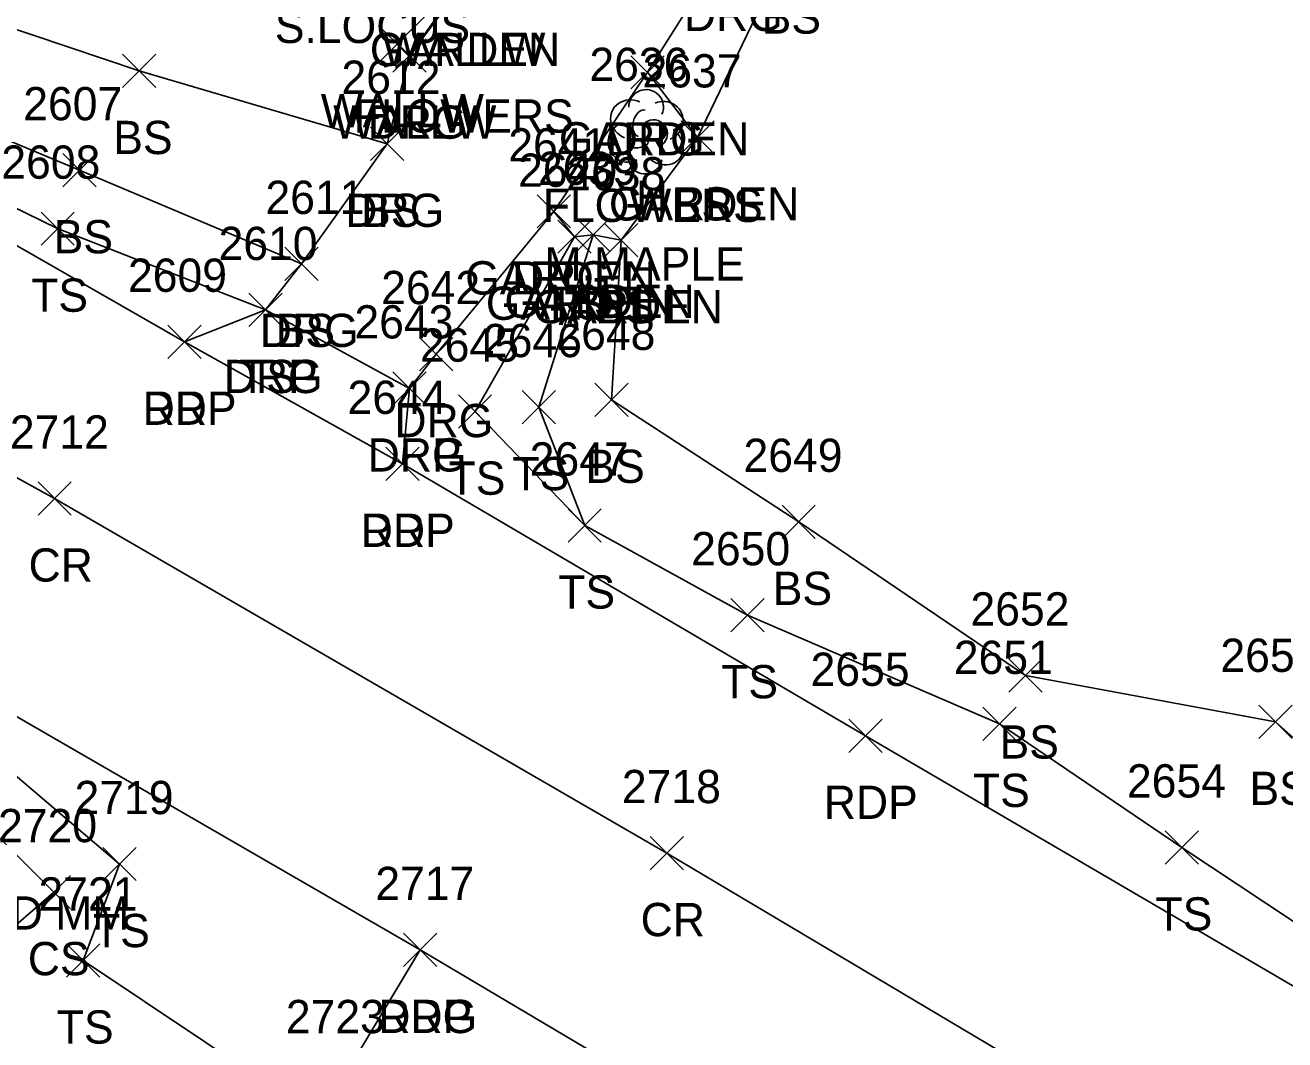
# Model space of a CAD drawing. Extents: x 1499292 to 1501024, y 534584 to 538043.
# Drawn here: x 1499592.5 to 1499668.2, y 537816.8 to 537877.8 of the extents above; entities that cross this region are included whole.
import ezdxf

# ---------------------------------------------------------------- set-up
doc = ezdxf.new("R2010")
doc.units = 0
for name, color, linetype in [('L_A', 7, 'Continuous'), ('L_C', 7, 'Continuous'), ('L_I', 7, 'Continuous'), ('L_TIC', 7, 'Continuous'), ('LAPB', 7, 'Continuous'), ('LELB', 7, 'Continuous'), ('LTD', 7, 'Continuous'), ('LW', 7, 'Continuous'), ('P_A', 7, 'Continuous'), ('P_I', 7, 'Continuous'), ('P_TIC', 7, 'Continuous'), ('PET', 7, 'Continuous'), ('PRC', 7, 'Continuous'), ('R_A', 7, 'Continuous'), ('R_C', 7, 'Continuous'), ('R_I', 7, 'Continuous'), ('R_TIC', 7, 'Continuous'), ('RDG', 7, 'Continuous'), ('RDP', 7, 'Continuous'), ('S_C', 7, 'Continuous')]:
    doc.layers.add(name, color=color, linetype=linetype)

msp = doc.modelspace()

# ---------------------------------------------------------------- linework, layer by layer
at = {"layer": 'L_TIC'}
for points in [[(1499613.859, 537875.659), (1499615.859, 537877.659)], [(1499615.859, 537875.659), (1499613.859, 537877.659)], [(1499614.61, 537874.966), (1499616.61, 537876.966)], [(1499616.61, 537874.966), (1499614.61, 537876.966)], [(1499598.362, 537874.044), (1499600.362, 537876.044)], [(1499600.362, 537874.044), (1499598.362, 537876.044)], [(1499628.919, 537873.961), (1499630.919, 537875.961)], [(1499630.919, 537873.961), (1499628.919, 537875.961)], [(1499613.263, 537869.665), (1499615.263, 537871.665)], [(1499615.263, 537869.665), (1499613.263, 537871.665)], [(1499631.925, 537870.051), (1499633.925, 537872.051)], [(1499633.925, 537870.051), (1499631.925, 537872.051)], [(1499631.925, 537870.051), (1499633.925, 537872.051)], [(1499633.925, 537870.051), (1499631.925, 537872.051)], [(1499594.778, 537868.076), (1499596.778, 537870.076)], [(1499596.778, 537868.076), (1499594.778, 537870.076)], [(1499623.289, 537865.6), (1499625.289, 537867.6)], [(1499625.289, 537865.6), (1499623.289, 537867.6)], [(1499593.46, 537864.561), (1499595.46, 537866.561)], [(1499595.46, 537864.561), (1499593.46, 537866.561)], [(1499624.53, 537864.077), (1499626.53, 537866.077)], [(1499626.53, 537864.077), (1499624.53, 537866.077)], [(1499624.53, 537864.077), (1499626.53, 537866.077)], [(1499626.53, 537864.077), (1499624.53, 537866.077)], [(1499625.646, 537864.191), (1499627.646, 537866.191)], [(1499627.646, 537864.191), (1499625.646, 537866.191)], [(1499625.646, 537864.191), (1499627.646, 537866.191)], [(1499627.646, 537864.191), (1499625.646, 537866.191)], [(1499627.34, 537863.862), (1499629.34, 537865.862)], [(1499629.34, 537863.862), (1499627.34, 537865.862)], [(1499627.34, 537863.862), (1499629.34, 537865.862)], [(1499629.34, 537863.862), (1499627.34, 537865.862)], [(1499608.124, 537862.443), (1499610.124, 537864.443)], [(1499610.124, 537862.443), (1499608.124, 537864.443)], [(1499605.958, 537859.671), (1499607.958, 537861.671)], [(1499607.958, 537859.671), (1499605.958, 537861.671)], [(1499626.747, 537854.268), (1499628.747, 537856.268)], [(1499628.747, 537854.268), (1499626.747, 537856.268)], [(1499626.747, 537854.268), (1499628.747, 537856.268)], [(1499628.747, 537854.268), (1499626.747, 537856.268)], [(1499618.548, 537853.557), (1499620.548, 537855.557)], [(1499620.548, 537853.557), (1499618.548, 537855.557)], [(1499622.386, 537853.831), (1499624.386, 537855.831)], [(1499624.386, 537853.831), (1499622.386, 537855.831)], [(1499625.141, 537846.711), (1499627.141, 537848.711)], [(1499627.141, 537846.711), (1499625.141, 537848.711)], [(1499625.141, 537846.711), (1499627.141, 537848.711)], [(1499627.141, 537846.711), (1499625.141, 537848.711)], [(1499638.004, 537846.929), (1499640.004, 537848.929)], [(1499640.004, 537846.929), (1499638.004, 537848.929)], [(1499634.935, 537841.316), (1499636.935, 537843.316)], [(1499636.935, 537841.316), (1499634.935, 537843.316)], [(1499651.639, 537837.691), (1499653.639, 537839.691)], [(1499653.639, 537837.691), (1499651.639, 537839.691)], [(1499650.071, 537834.781), (1499652.071, 537836.781)], [(1499652.071, 537834.781), (1499650.071, 537836.781)], [(1499666.661, 537834.904), (1499668.661, 537836.904)], [(1499668.661, 537834.904), (1499666.661, 537836.904)], [(1499661.043, 537827.35), (1499663.043, 537829.35)], [(1499663.043, 537827.35), (1499661.043, 537829.35)], [(1499597.177, 537826.35), (1499599.177, 537828.35)], [(1499599.177, 537826.35), (1499597.177, 537828.35)], [(1499593.227, 537824.662), (1499595.227, 537826.662)], [(1499595.227, 537824.662), (1499593.227, 537826.662)], [(1499595, 537820.552), (1499597, 537822.552)], [(1499597, 537820.552), (1499595, 537822.552)]]:
    msp.add_lwpolyline(points, dxfattribs=at)
at = {"layer": 'LAPB'}
msp.add_lwpolyline([(1499629.919, 537874.961), (1499632.925, 537871.051), (1499628.34, 537864.862), (1499626.646, 537865.191), (1499625.53, 537865.077), (1499624.289, 537866.6)], dxfattribs=at)
at = {"layer": 'LELB'}
for points in [[(1499309.186, 537981.429), (1499342.601, 537967.946), (1499383.002, 537948.454), (1499403.335, 537937.322), (1499425.862, 537923.972), (1499462.056, 537903.885), (1499477.958, 537896.437), (1499498.482, 537885.281), (1499524.089, 537871.298), (1499544.155, 537861.141), (1499587.091, 537836.791), (1499598.177, 537827.35), (1499596, 537821.552), (1499610.739, 537811.692), (1499624.068, 537800.087), (1499630.641, 537795.692), (1499636.949, 537791.6), (1499648.607, 537781.35)], [(1499660.231, 537903.009), (1499648.036, 537884.677), (1499638.338, 537882.285), (1499632.925, 537871.051)], [(1499566.448, 537888.249), (1499576.549, 537877.121), (1499595.778, 537869.076), (1499609.124, 537863.443)], [(1499565.054, 537884.662), (1499575.48, 537874.847), (1499594.46, 537865.561), (1499606.958, 537860.671)], [(1499584.328, 537880.125), (1499599.362, 537875.044), (1499614.263, 537870.665)], [(1499524.089, 537871.298), (1499543.469, 537857.463), (1499585.605, 537834.299), (1499594.227, 537825.662), (1499587.206, 537819.565)], [(1499625.53, 537865.077), (1499619.548, 537854.557), (1499626.141, 537847.711), (1499635.935, 537842.316), (1499651.071, 537835.781), (1499662.043, 537828.35), (1499682.408, 537814.83)], [(1499626.646, 537865.191), (1499623.386, 537854.831), (1499626.141, 537847.711)], [(1499628.34, 537864.862), (1499627.747, 537855.268)], [(1499627.747, 537855.268), (1499639.004, 537847.929), (1499652.639, 537838.691), (1499667.661, 537835.904), (1499684.96, 537820.495), (1499707.639, 537812.939), (1499721.619, 537803.525), (1499733.304, 537792.08), (1499740.748, 537784.702), (1499753.291, 537774.66), (1499768.462, 537764.036)]]:
    msp.add_lwpolyline(points, dxfattribs=at)
at = {"layer": 'LTD'}
msp.add_line((1499629.786, 537871.441), (1499629.786, 537871.441), dxfattribs=at)
msp.add_line((1499629.786, 537871.441), (1499629.786, 537871.441), dxfattribs=at)
msp.add_arc((1499629.833, 537872.875), 1.047, 335.52715, 180.95627, dxfattribs=at)
for centre, major_axis, ratio, start_param, end_param in [((1499628.994, 537872.107), (1.21, -0.512), 0.895232, 1.570796, 4.712389), ((1499630.828, 537872.024), (-1.141, -0.483), 0.949671, 1.570796, 4.712389), ((1499629.578, 537871.899), (-0.208, -0.792), 0.645439, 3.141593, 6.283185), ((1499630.286, 537871.274), (-0.5, 0.667), 0.989748, 3.141593, 6.283185), ((1499628.703, 537870.732), (0.584, -1.042), 0.959034, 3.141593, 6.283185), ((1499630.786, 537870.607), (-1.09, 0.792), 0.841452, 1.570796, 4.712389), ((1499629.328, 537870.69), (-0.625, -0.083), 0.423636, 0, 3.141593), ((1499629.786, 537869.941), (0.265, 1.061), 0.942809, 1.570796, 4.712389)]:
    msp.add_ellipse(centre, major_axis=major_axis, ratio=ratio, start_param=start_param, end_param=end_param, dxfattribs=at)
at = {"layer": 'LW'}
msp.add_lwpolyline([(1499618.556, 537880.336), (1499614.859, 537876.659), (1499615.61, 537875.966), (1499622.698, 537885.986), (1499629.881, 537895.602), (1499638.306, 537889.471)], dxfattribs=at)
at = {"layer": 'P_TIC'}
for points in [[(1499601.082, 537857.76), (1499603.082, 537859.76)], [(1499603.082, 537857.76), (1499601.082, 537859.76)], [(1499614.195, 537850.418), (1499616.195, 537852.418)], [(1499616.195, 537850.418), (1499614.195, 537852.418)], [(1499593.281, 537848.334), (1499595.281, 537850.334)], [(1499595.281, 537848.334), (1499593.281, 537850.334)], [(1499642.027, 537834.063), (1499644.027, 537836.063)], [(1499644.027, 537834.063), (1499642.027, 537836.063)], [(1499630.071, 537827.01), (1499632.071, 537829.01)], [(1499632.071, 537827.01), (1499630.071, 537829.01)], [(1499615.247, 537821.183), (1499617.247, 537823.183)], [(1499617.247, 537821.183), (1499615.247, 537823.183)]]:
    msp.add_lwpolyline(points, dxfattribs=at)
at = {"layer": 'PET'}
for points in [[(1499318.777, 538007.185), (1499356.077, 537991.329), (1499396.207, 537971.039), (1499437.012, 537950.167), (1499476.074, 537929.172), (1499509.306, 537910.677), (1499546.423, 537890.59), (1499566.293, 537879.272), (1499602.082, 537858.76), (1499615.195, 537851.418), (1499643.027, 537835.063), (1499676.234, 537815.623), (1499707.101, 537797.403), (1499725.198, 537785.865), (1499749.466, 537768.587), (1499768.247, 537754.161), (1499782.48, 537740.777), (1499805.279, 537716.472), (1499820.533, 537699.08)], [(1499310.023, 537983.746), (1499343.075, 537969.541), (1499383.731, 537949.439), (1499427.71, 537927.425), (1499464.171, 537907.983), (1499500.199, 537887.497), (1499544.495, 537863.142), (1499587.74, 537838.677), (1499616.247, 537822.183), (1499651.021, 537801.554), (1499676.536, 537785.628), (1499704.158, 537768.574), (1499722.55, 537756.398), (1499745.414, 537739.8), (1499767.298, 537722.36), (1499790.892, 537701.646), (1499806.057, 537686.036), (1499813.912, 537693.068), (1499820.533, 537699.08)]]:
    msp.add_lwpolyline(points, dxfattribs=at)
at = {"layer": 'PRC'}
msp.add_lwpolyline([(1499314.647, 537995.238), (1499351.896, 537980.059), (1499390.853, 537960.785), (1499432.771, 537938.063), (1499470.255, 537918.917), (1499503.529, 537899.736), (1499550.301, 537873.589), (1499594.281, 537849.334), (1499631.071, 537828.01), (1499665.93, 537807.267), (1499699.614, 537786.782), (1499728.317, 537767.815), (1499774.937, 537731.181), (1499796.918, 537710.716), (1499813.912, 537693.068)], dxfattribs=at)
at = {"layer": 'R_TIC'}
for points in [[(1499614.61, 537874.966), (1499616.61, 537876.966)], [(1499616.61, 537874.966), (1499614.61, 537876.966)], [(1499628.919, 537873.961), (1499630.919, 537875.961)], [(1499630.919, 537873.961), (1499628.919, 537875.961)], [(1499613.263, 537869.665), (1499615.263, 537871.665)], [(1499615.263, 537869.665), (1499613.263, 537871.665)], [(1499623.289, 537865.6), (1499625.289, 537867.6)], [(1499625.289, 537865.6), (1499623.289, 537867.6)], [(1499608.124, 537862.443), (1499610.124, 537864.443)], [(1499610.124, 537862.443), (1499608.124, 537864.443)], [(1499605.958, 537859.671), (1499607.958, 537861.671)], [(1499607.958, 537859.671), (1499605.958, 537861.671)], [(1499605.958, 537859.671), (1499607.958, 537861.671)], [(1499607.958, 537859.671), (1499605.958, 537861.671)], [(1499601.082, 537857.76), (1499603.082, 537859.76)], [(1499603.082, 537857.76), (1499601.082, 537859.76)], [(1499616.216, 537857.019), (1499618.216, 537859.019)], [(1499618.216, 537857.019), (1499616.216, 537859.019)], [(1499614.607, 537854.954), (1499616.607, 537856.954)], [(1499616.607, 537854.954), (1499614.607, 537856.954)], [(1499614.607, 537854.954), (1499616.607, 537856.954)], [(1499616.607, 537854.954), (1499614.607, 537856.954)], [(1499614.195, 537850.418), (1499616.195, 537852.418)], [(1499616.195, 537850.418), (1499614.195, 537852.418)], [(1499615.247, 537821.183), (1499617.247, 537823.183)], [(1499617.247, 537821.183), (1499615.247, 537823.183)]]:
    msp.add_lwpolyline(points, dxfattribs=at)
at = {"layer": 'RDG'}
for points in [[(1499606.958, 537860.671), (1499609.124, 537863.443), (1499614.263, 537870.665), (1499615.61, 537875.966), (1499622.932, 537885.698), (1499629.918, 537895.211), (1499638.306, 537889.471), (1499634.617, 537882.442), (1499629.919, 537874.961), (1499624.289, 537866.6), (1499617.216, 537858.019), (1499615.607, 537855.954)], [(1499616.247, 537822.183), (1499611.438, 537814.178), (1499627.998, 537804.719), (1499648.228, 537793.601), (1499657.65, 537787.037), (1499661.233, 537780.563), (1499662.782, 537771.708), (1499664.288, 537756.487), (1499660.39, 537740.632), (1499648.725, 537728.571), (1499635.519, 537714.664), (1499643.061, 537703.46), (1499654.084, 537709.775), (1499666.097, 537716.349), (1499687.017, 537701.096), (1499694.358, 537709.594), (1499686.467, 537716.113), (1499685.219, 537725.482), (1499686.936, 537727.795), (1499688.073, 537727.086)]]:
    msp.add_lwpolyline(points, dxfattribs=at)
at = {"layer": 'RDP'}
msp.add_lwpolyline([(1499602.082, 537858.76), (1499606.958, 537860.671), (1499615.607, 537855.954), (1499615.195, 537851.418)], dxfattribs=at)

# ---------------------------------------------------------------- texts
at = {"layer": 'L_A'}
for s, p in [('BS', (1499636.779, 537877.285)), ('GARDEN', (1499613.225, 537875.336)), ('WALLW', (1499613.973, 537875.336)), ('WALLW', (1499610.276, 537871.659)), ('WALLW', (1499611.027, 537870.966)), ('BS', (1499597.803, 537870.044)), ('GARDEN', (1499624.588, 537869.961)), ('H', (1499629.219, 537866.441)), ('BS', (1499612.703, 537865.665)), ('GARDEN', (1499627.594, 537866.051)), ('BS', (1499631.366, 537866.051)), ('BS', (1499594.219, 537864.076)), ('GARDEN', (1499618.958, 537861.6)), ('TS', (1499592.87, 537860.561)), ('GARDEN', (1499620.199, 537860.077)), ('GARDEN', (1499621.315, 537860.191)), ('GARDEN', (1499623.009, 537859.862)), ('TS', (1499623.94, 537860.077)), ('TS', (1499625.055, 537860.191)), ('BS', (1499626.781, 537859.862)), ('BS', (1499607.565, 537858.443)), ('TS', (1499605.368, 537855.671)), ('TS', (1499621.795, 537849.831)), ('BS', (1499626.188, 537850.268)), ('BS', (1499626.188, 537850.268)), ('TS', (1499617.957, 537849.557)), ('BS', (1499637.445, 537842.929)), ('TS', (1499624.551, 537842.711)), ('TS', (1499624.551, 537842.711)), ('TS', (1499634.345, 537837.316)), ('BS', (1499651.08, 537833.691)), ('TS', (1499649.48, 537830.781)), ('BS', (1499666.102, 537830.904)), ('TS', (1499660.452, 537823.35)), ('TS', (1499596.587, 537822.35)), ('CS', (1499592.668, 537820.662)), ('TS', (1499594.409, 537816.552))]:
    msp.add_text(s, height=2, dxfattribs=at).set_placement(p)
at = {"layer": 'L_C'}
for s, p in [('S.LOCUS', (1499607.514, 537876.722)), ('FLOWERS', (1499612.257, 537871.336)), ('M.MAPLE', (1499623.723, 537862.441))]:
    msp.add_text(s, height=2, dxfattribs=at).set_placement(p)
at = {"layer": 'L_I'}
for s, p in [('2636', (1499626.424, 537874.441)), ('2637', (1499629.618, 537874.051)), ('2637', (1499629.618, 537874.051)), ('2612', (1499611.522, 537873.665)), ('2607', (1499592.392, 537872.076)), ('2641', (1499621.549, 537869.6)), ('2608', (1499591.074, 537868.561)), ('2640', (1499622.136, 537868.077)), ('2640', (1499622.136, 537868.077)), ('2639', (1499623.331, 537868.191)), ('2639', (1499623.331, 537868.191)), ('2638', (1499625.033, 537867.862)), ('2638', (1499625.033, 537867.862)), ('2611', (1499606.951, 537866.443)), ('2610', (1499604.132, 537863.671)), ('2648', (1499624.44, 537858.268)), ('2648', (1499624.44, 537858.268)), ('2645', (1499616.24, 537857.557)), ('2646', (1499620.024, 537857.831)), ('2647', (1499622.834, 537850.711)), ('2647', (1499622.834, 537850.711)), ('2649', (1499635.689, 537850.929)), ('2650', (1499632.542, 537845.316)), ('2652', (1499649.332, 537841.691)), ('2651', (1499648.33, 537838.781)), ('2653', (1499664.354, 537838.904)), ('2654', (1499658.736, 537831.35)), ('2719', (1499595.476, 537830.35)), ('2720', (1499590.88, 537828.662)), ('2721', (1499593.307, 537824.552))]:
    msp.add_text(s, height=2, dxfattribs=at).set_placement(p)
at = {"layer": 'P_A'}
for s, p in [('RDP', (1499599.57, 537853.76)), ('RDP', (1499612.684, 537846.418)), ('CR', (1499592.714, 537844.334)), ('RDP', (1499640.515, 537830.063)), ('CR', (1499629.504, 537823.01)), ('RDP', (1499613.735, 537817.183))]:
    msp.add_text(s, height=2, dxfattribs=at).set_placement(p)
at = {"layer": 'P_I'}
for s, p in [('2609', (1499598.689, 537861.76)), ('2644', (1499611.888, 537854.418)), ('2712', (1499591.588, 537852.334)), ('2655', (1499639.72, 537838.063)), ('2718', (1499628.378, 537831.01)), ('2717', (1499613.554, 537825.183))]:
    msp.add_text(s, height=2, dxfattribs=at).set_placement(p)
at = {"layer": 'R_A'}
for s, p in [('DRG', (1499632.106, 537877.442)), ('DRG', (1499613.098, 537870.966)), ('DRG', (1499627.407, 537869.961)), ('DRG', (1499611.751, 537865.665)), ('DRG', (1499621.777, 537861.6)), ('DRG', (1499606.612, 537858.443)), ('DRG', (1499604.447, 537855.671)), ('DRP', (1499604.447, 537855.671)), ('DRP', (1499599.57, 537853.76)), ('DRG', (1499614.704, 537853.019)), ('DRG', (1499613.095, 537850.954)), ('DRP', (1499613.095, 537850.954)), ('DRP', (1499612.684, 537846.418)), ('DRG', (1499613.735, 537817.183))]:
    msp.add_text(s, height=2, dxfattribs=at).set_placement(p)
at = {"layer": 'R_C'}
msp.add_text('FLOWERS', height=2, dxfattribs=at).set_placement((1499623.62, 537865.961))
at = {"layer": 'R_I'}
for s, p in [('2612', (1499611.522, 537873.665)), ('2641', (1499621.549, 537869.6)), ('2611', (1499606.951, 537866.443)), ('2610', (1499604.132, 537863.671)), ('2610', (1499604.132, 537863.671)), ('2609', (1499598.689, 537861.76)), ('2642', (1499613.909, 537861.019)), ('2643', (1499612.3, 537858.954)), ('2643', (1499612.3, 537858.954)), ('2644', (1499611.888, 537854.418)), ('2717', (1499613.554, 537825.183)), ('2723', (1499608.178, 537817.178))]:
    msp.add_text(s, height=2, dxfattribs=at).set_placement(p)
at = {"layer": 'S_C'}
msp.add_text('INTERSECTION AND MM', height=2, dxfattribs=at).set_placement((1499567.27, 537823.408))

doc.saveas('drawing.dxf')
